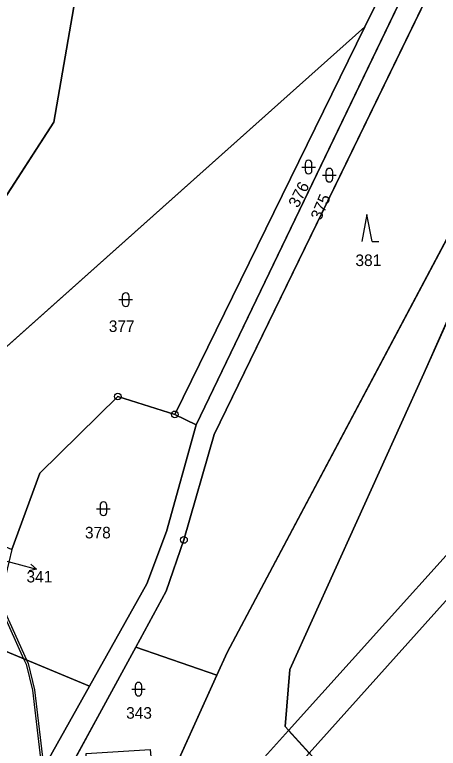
# Model space of a CAD drawing. Extents: x -689422 to -685210, y -987725 to -982160.
# Drawn here: x -686646.8 to -686584.5, y -986778.6 to -986670.9 of the extents above; entities that cross this region are included whole.
import ezdxf

# ---------------------------------------------------------------- set-up
doc = ezdxf.new("R2010")
doc.units = 0
for name, color, linetype in [('KN_Hranice_parcel', 7, 'Continuous'), ('KN_Parcelni cisla', 7, 'Continuous'), ('KN_Parcelni cisla_sipky', 7, 'Continuous'), ('KN_Polygon parcely', 7, 'Continuous'), ('KN_POZEMKY_LESNI POZEMEK', 7, 'Continuous'), ('KN_POZEMKY_ORNA PUDA', 7, 'Continuous'), ('KN_POZEMKY_OSTATNI PLOCHA', 7, 'Continuous'), ('KN_POZEMKY_TTP', 7, 'Continuous'), ('KN_POZEMKY_VODNI_PLOCHA', 7, 'Continuous'), ('KN_POZEMKY_ZASTAVENA PLOCHA', 7, 'Continuous'), ('KN_VYUZITI_07_vodni plocha_tok prirozeny', 7, 'Continuous'), ('KN_VYUZITI_13_zastavena plocha_zboreniste', 7, 'Continuous'), ('KN_VYUZITI_27_ostatni plocha_neplodna puda', 7, 'Continuous'), ('KN_Věcná břemena k části', 7, 'Continuous'), ('KN_Značky bodu BP', 7, 'Continuous'), ('KN_Značky kultur', 7, 'Continuous')]:
    doc.layers.add(name, color=color, linetype=linetype)

msp = doc.modelspace()

# ---------------------------------------------------------------- linework, layer by layer
at = {"layer": 'KN_Hranice_parcel'}
for p, q in [((-686595.28, -986672.65), (-686590.34, -986662.59)), ((-686665.7, -986735.44), (-686595.28, -986672.65)), ((-686623.22, -986729.58), (-686595.28, -986672.65)), ((-686631.6, -986726.95), (-686623.22, -986729.58)), ((-686620.08, -986731.12), (-686623.22, -986729.58)), ((-686624.52, -986755.54), (-686621.89, -986748.01)), ((-686627.33, -986754.48), (-686635.76, -986769.5)), ((-686628.97, -986763.74), (-686624.52, -986755.54)), ((-686628.97, -986763.74), (-686640.64, -986785.22)), ((-686617.03, -986767.88), (-686628.97, -986763.74)), ((-686615.53, -986764.56), (-686617.03, -986767.88)), ((-686623.7, -986782.59), (-686617.03, -986767.88))]:
    msp.add_line(p, q, dxfattribs=at)
for points in [[(-686514.6, -986555.75), (-686520.7, -986581.19), (-686524.77, -986591.31), (-686548.81, -986631.14), (-686545.48, -986632.64), (-686615.53, -986764.56)], [(-686621.89, -986748.01), (-686617.44, -986732.54), (-686584.85, -986665.54), (-686546.91, -986614.92), (-686539.48, -986589.87), (-686532.26, -986564.85)], [(-686541.35, -986566.19), (-686547.17, -986567.66), (-686561.95, -986581.11), (-686565.92, -986601.15), (-686576.68, -986618.58), (-686608, -986632.87), (-686637.86, -986668.52), (-686641.01, -986686.64), (-686660.93, -986717.42), (-686670.75, -986725.07), (-686685.88, -986729.98), (-686686.11, -986736.82)], [(-686537.28, -986565.66), (-686542.74, -986588.77), (-686549.72, -986612.83), (-686587.69, -986663.84), (-686620.08, -986731.12)], [(-686562.1, -986800.53), (-686587.68, -986796.64), (-686607.02, -986775.42), (-686606.32, -986767.03), (-686586.61, -986723.58), (-686570.06, -986686.25)], [(-686647.19, -986749.4), (-686643.07, -986738.2), (-686631.6, -986726.95)], [(-686620.08, -986731.12), (-686624.43, -986746.77), (-686627.33, -986754.48)], [(-686635.76, -986769.5), (-686649.32, -986763.85), (-686648.52, -986754.99)], [(-686662.92, -986781.9), (-686647.28, -986782.27), (-686643.01, -986782.41), (-686635.76, -986769.5)]]:
    msp.add_lwpolyline(points, dxfattribs=at)
at = {"layer": 'KN_Parcelni cisla_sipky'}
for p, q in [((-686648.9, -986750.9), (-686646.44, -986751.54)), ((-686646.44, -986751.54), (-686643.54, -986752.32)), ((-686643.54, -986752.32), (-686644.38, -986751.57)), ((-686643.54, -986752.32), (-686644.64, -986752.54))]:
    msp.add_line(p, q, dxfattribs=at)
at = {"layer": 'KN_Polygon parcely'}
for points in [[(-686726.31, -986778.54), (-686709.75, -986769.81), (-686703.89, -986756.61), (-686689.2, -986743.77), (-686688.89, -986743.08), (-686686.47, -986737.62), (-686686.11, -986736.82), (-686685.88, -986729.98), (-686670.75, -986725.07), (-686660.93, -986717.42), (-686641.01, -986686.64), (-686637.86, -986668.52), (-686608, -986632.87), (-686576.68, -986618.58), (-686565.92, -986601.15), (-686561.95, -986581.11), (-686547.17, -986567.66), (-686541.35, -986566.19), (-686537.28, -986565.66), (-686532.26, -986564.85), (-686529.76, -986542.24), (-686530.23, -986465.49)], [(-686587.69, -986663.84), (-686620.08, -986731.12), (-686624.43, -986746.77), (-686627.33, -986754.48), (-686635.76, -986769.5), (-686643.01, -986782.41), (-686647.28, -986782.27), (-686662.92, -986781.9), (-686674.64, -986806.58), (-686671.68, -986816.66), (-686681.76, -986829.17), (-686691.17, -986852.38), (-686684.89, -986866.29)], [(-686683.77, -986859.67), (-686687.52, -986850.74), (-686679.02, -986830.76), (-686667.8, -986817.71), (-686671.32, -986808.24), (-686661.48, -986785), (-686645.96, -986786.61), (-686640.64, -986785.22), (-686628.97, -986763.74), (-686624.52, -986755.54), (-686621.89, -986748.01), (-686617.44, -986732.54), (-686584.85, -986665.54)]]:
    msp.add_lwpolyline(points, dxfattribs=at)
for points in [[(-686562.1, -986800.53), (-686356.47, -986773.74), (-686335.84, -986780.59), (-686317.15, -986737.15), (-686283.4, -986653.69), (-686347.32, -986530.39), (-686511.01, -986578.37), (-686521.37, -986607.92), (-686544.09, -986665.61), (-686570.06, -986686.25), (-686586.61, -986723.58), (-686606.32, -986767.03), (-686607.02, -986775.42), (-686587.68, -986796.64)], [(-686529.76, -986542.24), (-686532.26, -986564.85), (-686539.48, -986589.87), (-686546.91, -986614.92), (-686584.85, -986665.54), (-686617.44, -986732.54), (-686621.89, -986748.01), (-686624.52, -986755.54), (-686628.97, -986763.74), (-686617.03, -986767.88), (-686615.53, -986764.56), (-686545.48, -986632.64), (-686548.81, -986631.14), (-686524.77, -986591.31), (-686520.7, -986581.19), (-686514.6, -986555.75), (-686518.23, -986552.13)], [(-686521.37, -986607.92), (-686511.01, -986578.37), (-686509.94, -986575.81), (-686507.21, -986559.72), (-686509.24, -986560.47), (-686514.6, -986555.75), (-686520.7, -986581.19), (-686524.77, -986591.31), (-686548.81, -986631.14), (-686545.48, -986632.64), (-686615.53, -986764.56), (-686617.03, -986767.88), (-686623.7, -986782.59), (-686631.18, -986806.01), (-686625.14, -986808.3), (-686610.87, -986806.46), (-686579.72, -986802.83), (-686562.1, -986800.53), (-686587.68, -986796.64), (-686607.02, -986775.42), (-686606.32, -986767.03), (-686586.61, -986723.58), (-686570.06, -986686.25), (-686544.09, -986665.61)], [(-686595.28, -986672.65), (-686590.34, -986662.59), (-686552.4, -986611.39), (-686545.33, -986587.91), (-686541.35, -986566.19), (-686547.17, -986567.66), (-686561.95, -986581.11), (-686565.92, -986601.15), (-686576.68, -986618.58), (-686608, -986632.87), (-686637.86, -986668.52), (-686641.01, -986686.64), (-686660.93, -986717.42), (-686670.75, -986725.07), (-686685.88, -986729.98), (-686686.11, -986736.82), (-686683.38, -986736.82), (-686683.35, -986732.92), (-686678.35, -986732.97), (-686665.7, -986735.44)], [(-686541.35, -986566.19), (-686545.33, -986587.91), (-686552.4, -986611.39), (-686590.34, -986662.59), (-686595.28, -986672.65), (-686623.22, -986729.58), (-686620.08, -986731.12), (-686587.69, -986663.84), (-686549.72, -986612.83), (-686542.74, -986588.77), (-686537.28, -986565.66)], [(-686631.6, -986726.95), (-686623.22, -986729.58), (-686595.28, -986672.65), (-686665.7, -986735.44), (-686653.58, -986742.54), (-686650.25, -986748.07), (-686647.19, -986749.4), (-686643.07, -986738.2)], [(-686627.33, -986754.48), (-686624.43, -986746.77), (-686620.08, -986731.12), (-686623.22, -986729.58), (-686631.6, -986726.95), (-686643.07, -986738.2), (-686647.19, -986749.4), (-686648.52, -986754.99), (-686649.32, -986763.85), (-686635.76, -986769.5)], [(-686643.01, -986782.41), (-686635.76, -986769.5), (-686649.32, -986763.85), (-686648.52, -986754.99), (-686655.23, -986756.09), (-686658.98, -986750.76), (-686664.16, -986750.78), (-686669.76, -986751.7), (-686675.53, -986783.03), (-686672.63, -986783.15), (-686672.63, -986786.36), (-686667.21, -986786.24), (-686662.92, -986781.9), (-686647.28, -986782.27)], [(-686631.82, -986784.59), (-686631.35, -986792.15), (-686640.16, -986792.94), (-686639.67, -986800.72), (-686631.18, -986806.01), (-686623.7, -986782.59), (-686617.03, -986767.88), (-686628.97, -986763.74), (-686640.64, -986785.22), (-686635.97, -986784.99), (-686636.27, -986779.37), (-686626.87, -986778.78), (-686626.37, -986784.26)]]:
    msp.add_lwpolyline(points, close=True, dxfattribs=at)
at = {"layer": 'KN_POZEMKY_LESNI POZEMEK'}
for p, q in [((-686545.48, -986632.64), (-686615.53, -986764.56)), ((-686617.44, -986732.54), (-686584.85, -986665.54)), ((-686621.89, -986748.01), (-686617.44, -986732.54)), ((-686624.52, -986755.54), (-686621.89, -986748.01)), ((-686628.97, -986763.74), (-686624.52, -986755.54)), ((-686617.03, -986767.88), (-686628.97, -986763.74)), ((-686615.53, -986764.56), (-686617.03, -986767.88))]:
    msp.add_line(p, q, dxfattribs=at)
at = {"layer": 'KN_POZEMKY_ORNA PUDA'}
for p, q in [((-686586.61, -986723.58), (-686570.06, -986686.25)), ((-686606.32, -986767.03), (-686586.61, -986723.58)), ((-686607.02, -986775.42), (-686606.32, -986767.03)), ((-686587.68, -986796.64), (-686607.02, -986775.42))]:
    msp.add_line(p, q, dxfattribs=at)
at = {"layer": 'KN_POZEMKY_OSTATNI PLOCHA'}
for p, q in [((-686595.28, -986672.65), (-686590.34, -986662.59)), ((-686620.08, -986731.12), (-686587.69, -986663.84)), ((-686587.69, -986663.84), (-686620.08, -986731.12)), ((-686584.85, -986665.54), (-686617.44, -986732.54)), ((-686665.7, -986735.44), (-686595.28, -986672.65)), ((-686623.22, -986729.58), (-686595.28, -986672.65)), ((-686595.28, -986672.65), (-686623.22, -986729.58)), ((-686631.6, -986726.95), (-686643.07, -986738.2)), ((-686643.07, -986738.2), (-686631.6, -986726.95)), ((-686623.22, -986729.58), (-686631.6, -986726.95)), ((-686631.6, -986726.95), (-686623.22, -986729.58)), ((-686620.08, -986731.12), (-686623.22, -986729.58)), ((-686623.22, -986729.58), (-686620.08, -986731.12)), ((-686624.43, -986746.77), (-686620.08, -986731.12)), ((-686620.08, -986731.12), (-686624.43, -986746.77)), ((-686617.44, -986732.54), (-686621.89, -986748.01)), ((-686643.07, -986738.2), (-686647.19, -986749.4)), ((-686647.19, -986749.4), (-686643.07, -986738.2)), ((-686627.33, -986754.48), (-686624.43, -986746.77)), ((-686624.43, -986746.77), (-686627.33, -986754.48)), ((-686621.89, -986748.01), (-686624.52, -986755.54)), ((-686635.76, -986769.5), (-686627.33, -986754.48)), ((-686627.33, -986754.48), (-686635.76, -986769.5)), ((-686624.52, -986755.54), (-686628.97, -986763.74)), ((-686635.76, -986769.5), (-686649.32, -986763.85)), ((-686628.97, -986763.74), (-686640.64, -986785.22)), ((-686640.64, -986785.22), (-686628.97, -986763.74)), ((-686628.97, -986763.74), (-686617.03, -986767.88)), ((-686617.03, -986767.88), (-686623.7, -986782.59)), ((-686643.01, -986782.41), (-686635.76, -986769.5))]:
    msp.add_line(p, q, dxfattribs=at)
at = {"layer": 'KN_POZEMKY_TTP'}
for p, q in [((-686615.53, -986764.56), (-686545.48, -986632.64)), ((-686590.34, -986662.59), (-686595.28, -986672.65)), ((-686641.01, -986686.64), (-686637.86, -986668.52)), ((-686595.28, -986672.65), (-686665.7, -986735.44)), ((-686660.93, -986717.42), (-686641.01, -986686.64)), ((-686570.06, -986686.25), (-686586.61, -986723.58)), ((-686586.61, -986723.58), (-686606.32, -986767.03)), ((-686617.03, -986767.88), (-686615.53, -986764.56)), ((-686623.7, -986782.59), (-686617.03, -986767.88)), ((-686606.32, -986767.03), (-686607.02, -986775.42)), ((-686607.02, -986775.42), (-686587.68, -986796.64))]:
    msp.add_line(p, q, dxfattribs=at)
at = {"layer": 'KN_POZEMKY_VODNI_PLOCHA'}
for p, q in [((-686637.86, -986668.52), (-686641.01, -986686.64)), ((-686641.01, -986686.64), (-686660.93, -986717.42))]:
    msp.add_line(p, q, dxfattribs=at)
at = {"layer": 'KN_POZEMKY_ZASTAVENA PLOCHA'}
for p, q in [((-686649.32, -986763.85), (-686635.76, -986769.5)), ((-686635.76, -986769.5), (-686643.01, -986782.41))]:
    msp.add_line(p, q, dxfattribs=at)
at = {"layer": 'KN_VYUZITI_07_vodni plocha_tok prirozeny'}
for p, q in [((-686637.86, -986668.52), (-686641.01, -986686.64)), ((-686641.01, -986686.64), (-686660.93, -986717.42))]:
    msp.add_line(p, q, dxfattribs=at)
at = {"layer": 'KN_VYUZITI_13_zastavena plocha_zboreniste'}
for p, q in [((-686649.32, -986763.85), (-686635.76, -986769.5)), ((-686635.76, -986769.5), (-686643.01, -986782.41))]:
    msp.add_line(p, q, dxfattribs=at)
at = {"layer": 'KN_VYUZITI_27_ostatni plocha_neplodna puda'}
for p, q in [((-686595.28, -986672.65), (-686590.34, -986662.59)), ((-686620.08, -986731.12), (-686587.69, -986663.84)), ((-686587.69, -986663.84), (-686620.08, -986731.12)), ((-686584.85, -986665.54), (-686617.44, -986732.54)), ((-686665.7, -986735.44), (-686595.28, -986672.65)), ((-686623.22, -986729.58), (-686595.28, -986672.65)), ((-686595.28, -986672.65), (-686623.22, -986729.58)), ((-686631.6, -986726.95), (-686643.07, -986738.2)), ((-686643.07, -986738.2), (-686631.6, -986726.95)), ((-686623.22, -986729.58), (-686631.6, -986726.95)), ((-686631.6, -986726.95), (-686623.22, -986729.58)), ((-686620.08, -986731.12), (-686623.22, -986729.58)), ((-686623.22, -986729.58), (-686620.08, -986731.12)), ((-686624.43, -986746.77), (-686620.08, -986731.12)), ((-686620.08, -986731.12), (-686624.43, -986746.77)), ((-686617.44, -986732.54), (-686621.89, -986748.01)), ((-686643.07, -986738.2), (-686647.19, -986749.4)), ((-686647.19, -986749.4), (-686643.07, -986738.2)), ((-686627.33, -986754.48), (-686624.43, -986746.77)), ((-686624.43, -986746.77), (-686627.33, -986754.48)), ((-686621.89, -986748.01), (-686624.52, -986755.54)), ((-686635.76, -986769.5), (-686627.33, -986754.48)), ((-686627.33, -986754.48), (-686635.76, -986769.5)), ((-686624.52, -986755.54), (-686628.97, -986763.74)), ((-686635.76, -986769.5), (-686649.32, -986763.85)), ((-686628.97, -986763.74), (-686640.64, -986785.22)), ((-686640.64, -986785.22), (-686628.97, -986763.74)), ((-686628.97, -986763.74), (-686617.03, -986767.88)), ((-686617.03, -986767.88), (-686623.7, -986782.59)), ((-686643.01, -986782.41), (-686635.76, -986769.5))]:
    msp.add_line(p, q, dxfattribs=at)
at = {"layer": 'KN_Věcná břemena k části'}
for points in [[(-686606.5, -986776), (-686603.46, -986779.33), (-686527.61, -986694.77), (-686382.46, -986540.69), (-686394.63, -986544.26), (-686530.79, -986691.97)], [(-686645.44, -986765.46), (-686644.97, -986765.66), (-686647.42, -986760.23), (-686648.73, -986757.32), (-686648.79, -986758.02), (-686647.51, -986760.88)], [(-686643.78, -986770.02), (-686644.75, -986766.14), (-686644.95, -986765.7), (-686644.97, -986765.66), (-686645.44, -986765.46), (-686645.09, -986766.26), (-686644.12, -986770.08), (-686642.82, -986781.4), (-686642.75, -986781.95), (-686642.47, -986781.44), (-686642.54, -986780.75)], [(-686629.88, -986801.96), (-686631.18, -986806.01), (-686628.35, -986807.08), (-686603.46, -986779.33), (-686606.5, -986776)]]:
    msp.add_lwpolyline(points, close=True, dxfattribs=at)
at = {"layer": 'KN_Značky bodu BP'}
for centre, radius in [((-686631.6, -986726.95), 0.5), ((-686631.6, -986726.95), 0.0303), ((-686623.22, -986729.58), 0.5), ((-686623.22, -986729.58), 0.0303), ((-686621.89, -986748.01), 0.5), ((-686621.89, -986748.01), 0.0303)]:
    msp.add_circle(centre, radius, dxfattribs=at)
at = {"layer": 'KN_Značky kultur'}
for p, q in [((-686604.57, -986693.25), (-686602.57, -986693.25)), ((-686604.07, -986692.75), (-686604.07, -986693.75)), ((-686603.07, -986693.75), (-686603.07, -986692.75)), ((-686601.51, -986694.44), (-686599.51, -986694.44)), ((-686601.01, -986693.94), (-686601.01, -986694.94)), ((-686600.01, -986694.94), (-686600.01, -986693.94)), ((-686594.99, -986700.2), (-686595.74, -986704.2)), ((-686594.24, -986704.2), (-686594.99, -986700.2)), ((-686594.24, -986704.2), (-686593.24, -986704.2)), ((-686631.44, -986712.71), (-686629.44, -986712.71)), ((-686630.94, -986712.21), (-686630.94, -986713.21)), ((-686629.94, -986713.21), (-686629.94, -986712.21)), ((-686634.21, -986742.93), (-686634.21, -986743.93)), ((-686633.21, -986743.93), (-686633.21, -986742.93)), ((-686634.71, -986743.43), (-686632.71, -986743.43)), ((-686629.56, -986769.93), (-686627.56, -986769.93)), ((-686629.06, -986769.43), (-686629.06, -986770.43)), ((-686628.06, -986770.43), (-686628.06, -986769.43))]:
    msp.add_line(p, q, dxfattribs=at)
for centre, start, end in [((-686603.57, -986692.75), 0, 180), ((-686600.51, -986693.94), 0, 180), ((-686603.57, -986693.75), 180, 359.9879), ((-686600.51, -986694.94), 180, 359.9879), ((-686630.44, -986712.21), 0, 180), ((-686630.44, -986713.21), 180, 359.9879), ((-686633.71, -986742.93), 0, 180), ((-686633.71, -986743.93), 180, 359.9879), ((-686628.56, -986769.43), 0, 180), ((-686628.56, -986770.43), 180, 359.9879)]:
    msp.add_arc(centre, 0.5, start, end, dxfattribs=at)

# ---------------------------------------------------------------- texts
at = {"layer": 'KN_Parcelni cisla'}
for s, rotation, p in [('376', 63, (-686605.12, -986699.35)), ('375', 67, (-686601.78, -986701.18))]:
    msp.add_text(s, height=1.7, rotation=rotation, dxfattribs=at).set_placement(p)
for s, p in [('381', (-686596.68, -986707.79)), ('377', (-686632.93, -986717.47)), ('378', (-686636.43, -986747.79)), ('341', (-686645.02, -986754.26)), ('343', (-686630.38, -986774.27))]:
    msp.add_text(s, height=1.7, dxfattribs=at).set_placement(p)

doc.saveas('drawing.dxf')
